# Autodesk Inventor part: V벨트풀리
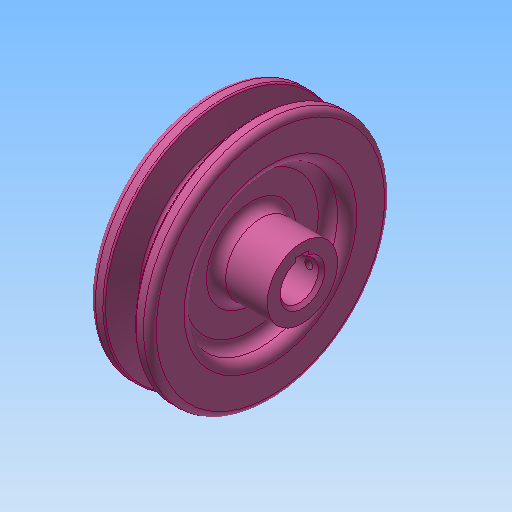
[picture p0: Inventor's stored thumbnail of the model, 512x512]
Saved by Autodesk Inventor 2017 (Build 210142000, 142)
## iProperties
Created: 2015-11
Part Number: V벨트풀리
Material: 강철, 탄소
Document SubType Name: Modeling
Designer: mduedu
Density: 1 g/cm^3
Appearance: 분홍색
Author: mduedu
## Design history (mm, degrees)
sketch "스케치1"
  geometry: L1 (-9.5, 0)-(9.5, 0); L2 (0, 0)-(0, 37.7); L3 (-4.825, 37.7)-(-9.5, 37.7); L4 (-9.5, 37.7)-(-9.5, 0); L5 (0, 28.7)-(-2.074, 28.7); L6 (-2.074, 28.7)-(-4.825, 37.7); L7 (4.825, 37.7)-(9.5, 37.7); L8 (9.5, 37.7)-(9.5, 0); L9 (0, 28.7)-(2.074, 28.7); L10 (2.074, 28.7)-(4.825, 37.7); L11 (-9.5, 35)-(9.5, 35); 3 further points
  constraints: 22 end point, 7 point on line, 4 perpendicular, 3 symmetric about line, 1 coincident, 1 horizontal, 1 horizontal alignment, 1 midpoint, 1 vertical
  dimensions: "d0" = 19 distance of L1.start L1.end; "d2" = 75.4 diameter of L2.end L1 (derived); "d3" = 34 deg angle of L10 L6; "d4" = 6.3 distance between parallel lines of L11 L9; "d5" = 2.7 distance between parallel lines of L7 L11; "d6" = 8 distance of point (4, 35) point (-4, 35); "d7" = 70 diameter of L11 L1
revolve "회전1" sketch "스케치1" stored, may be unused: angle "d8" = 90 deg
sketch "스케치2"
  geometry: C1 r 24 at (0, 0); C2 r 11 at (0, 0); 1 further point
  constraints: 2 centre point, 2 coincident
  dimensions: "d9" = 48 diameter of C1; "d10" = 22 diameter of C2
extrude "돌출1" cut sketch "스케치2" distance "d11" = 6; taper "d12" = 0 deg
extrude "돌출3" join sketch "스케치2" distance "d37" = 10; taper "d38" = 0 deg
fillet "모깎기1" dims "d13" = 3
fillet "모깎기2" dims "d14" = 3
fillet "모깎기3" dims "d15" = 1, "d16" = 0.5, "d17" = 2
hole "구멍1" diameter "d20" = 12; stored, may be unused: countersink angle "d24" = 90 deg, drill point angle "d26" = 118 deg; dims "d21" = 6, "d22" = 4, "d23" = 2, "d25" = 8, "d39" = 10, "d40" = 10
sketch "스케치3"
  geometry: L1 (-2, 0)-(2, 0); L2 (2, 0)-(2, 7.8); L3 (2, 7.8)-(-2, 7.8); L4 (-2, 7.8)-(-2, 0); 2 further points
  constraints: 8 end point, 2 parallel, 1 coincident, 1 horizontal, 1 midpoint, 1 perpendicular
  dimensions: "d27" = 4 distance of L2.end L3.end; "d29" = 7.8 distance of L3.end L1.start
extrude "돌출2" cut sketch "스케치3" stored distance "d30" = 6; taper "d31" = 0 deg
chamfer "모따기1" distance "d32" = 1; stored, may be unused: second distance "d33" = 2, angle "d34" = 45 deg
node "작업 평면1"
sketch "스케치4"
  geometry: L1 (-19, 11)-(-19, -11) reference; 2 further points
  constraints: 1 horizontal alignment
  dimensions: "d41" = 25 distance from line of point (6, 0) L1
hole "구멍2" sketch "스케치4" at (6, 0) diameter "d42" = 2.459; stored, may be unused: countersink angle "d46" = 90 deg, drill point angle "d48" = 118 deg; dims "d43" = 6, "d44" = 4, "d45" = 2, "d47" = 8
chamfer "모따기2" distance "d49" = 1; stored, may be unused: second distance "d50" = 2, angle "d51" = 45 deg
node "솔리드1"
mirror "대칭1"
